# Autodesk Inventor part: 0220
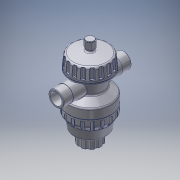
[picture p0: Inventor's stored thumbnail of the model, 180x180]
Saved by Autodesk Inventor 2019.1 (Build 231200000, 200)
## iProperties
Created: 2017-02
Part Number: 0220
Material: PVC-Piping
Document SubType Name: Modeling
Designer: KIM
Density: 1.4 g/cm^3
Appearance: PTFE
Mass: 92.6774 g
Surface Area: 199.44 cm^2
Volume: 66.1981 cm^3
Description: Universal Pressure Regulator UPR 550
Author: KIM
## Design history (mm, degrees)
sketch "Sketch4"
  geometry: L1 (0, 0)-(192, 0); L2 (192, 0)-(192, -8.05); L3 (190.3, -9.75)-(176.5, -9.75); L4 (176.5, -9.75)-(176.5, -6.75); L5 (176.5, -6.75)-(170.8, -6.75); L6 (170.8, -6.75)-(165.8, -40); L7 (165.8, -40)-(141.8, -42.5); L8 (105.5, -27.8)-(92.5, -45.5); L9 (57.7, -45.25)-(46.9, -38); L10 (46.9, -38)-(24.2, -34); L11 (24.2, -34)-(24.2, -22.8); L12 (24.2, -22.8)-(0, -22.8); L13 (0, -22.8)-(0, 0); L14 (192, -8.05)-(190.3, -8.05); L15 (190.3, -8.05)-(190.3, -9.75); L16 (141.8, -42.5)-(138.8, -42.5); L17 (138.8, -42.5)-(138.8, -41.8); L18 (138.8, -41.8)-(137.8, -41.8); L19 (137.8, -41.8)-(137.8, -42.5); L20 (137.8, -42.5)-(136, -42.5); L21 (136, -42.5)-(130, -30.5); L22 (72.7, -45.5)-(72.7, -44.55); L23 (72.7, -44.55)-(71.7, -44.55); L24 (71.7, -44.55)-(71.7, -45.25); L25 (92.5, -45.5)-(72.7, -45.5); L26 (71.7, -45.25)-(57.7, -45.25); L27 (116, 73)-(116, -73); L28 (132.625, -73)-(132.625, -53); L29 (132.625, -53)-(133.25, -53); L30 (133.25, -53)-(133.25, -52); L31 (133.25, -52)-(128.625, -52); L32 (128.625, -52)-(128.625, -73); L33 (128.625, -73)-(132.625, -73); L34 (105.5, -27.8)-(130, -30.5); 1 further point
  constraints: 68 end point, 19 perpendicular, 5 horizontal, 4 point on line, 4 vertical, 1 midpoint
  dimensions: "d51" = 192 distance of L1.start L1.end; "d53" = 19.5 diameter of L3 L1; "d54" = 1.7 distance of L14.end L3.start; "d55" = 1.7 distance of L2.end L14.end; "d56" = 15.5 distance between parallel lines of L2 L4; "d57" = 5.7 distance of L4.end L5.end; "d58" = 13.5 diameter of L5 L1; "d59" = 80 diameter of L6.end L1; "d60" = 5 horizontal distance of L5.end L6.end; "d61" = 2.5 vertical distance of L6.end L7.end; "d62" = 1.8 distance of L19.end L20.end; "d63" = 1 distance of L17.end L18.end; "d64" = 0.7 distance of L18.end L19.end; "d65" = 3 distance of L7.end L16.end; "d66" = 24 horizontal distance of L6.end L7.end; "d67" = 12 vertical distance of L20.end L21.end; "d68" = 6 horizontal distance of L20.end L21.end; "d70" = 24.5 horizontal distance of L8.start L21.end; "d71" = 2.7 vertical distance of L21.end L8.start; "d72" = 13 horizontal distance of L8.start L8.end; "d73" = 1 distance of L22.end L23.end; "d74" = 0.7 distance of L23.end L24.end; "d75" = 19.8 distance of L8.end L22.start; "d76" = 14 distance of L24.end L9.start; "d77" = 91 diameter of L25 L1; "d78" = 7.25 vertical distance of L9.start L9.end; "d79" = 10.8 horizontal distance of L9.start L9.end; "d80" = 22.7 horizontal distance of L9.end L10.end; "d81" = 68 diameter of L10.end L1; "d82" = 76 diameter of L9.end L1; "d83" = 45.6 diameter of L12 L1; "d84" = 146 distance of L27.start L27.end; "d85" = 116 distance of L1.start point (116, 0); "d86" = 20 distance of L28.start L28.end; "d87" = 33.249 diameter of L28 L27; "d88" = 4 distance of L32.end L28.start; "d90" = 34.5 diameter of L30 L27; "d91" = 1 distance of L29.end L30.end
revolve "Revolution2" stored, may be unused: angle "d92" = 90 deg
revolve "Revolution3" stored, may be unused: angle "d93" = 90 deg
sketch "Sketch5"
  geometry: L1 (0, 9.75)-(8.444, 4.875); L2 (8.444, 4.875)-(8.444, -4.875); L3 (8.444, -4.875)-(0, -9.75); L4 (0, -9.75)-(-8.444, -4.875); L5 (-8.444, -4.875)-(-8.444, 4.875); L6 (-8.444, 4.875)-(0, 9.75); L7 (0, 0)-(0, 9.75); 2 further points
  constraints: 14 end point, 1 coincident, 1 vertical, 1 vertical alignment, 14 other
extrude "Extrusion3" cut sketch "Sketch5" stored distance "d94" = 10; taper "d95" = 0 deg
fillet "Fillet5" dims "d96" = 5
fillet "Fillet6" dims "d97" = 4
sketch "Sketch6"
  geometry: L1 (0, 0)-(-66.727, 0); L2 (-42.5, -4)-(-42.5, 4); L3 (-42.5, 4)-(-41, 4); L4 (-39, 2)-(-39, -2); L5 (-41, -4)-(-42.5, -4); A1 r 2 centre (-41, 2) between (-39, 2) and (-41, 4); A2 r 2 centre (-41, -2) between (-41, -4) and (-39, -2); 2 further points
  constraints: 10 end point, 4 point on circle, 4 tangent, 3 perpendicular, 2 centre point, 1 equal radius, 1 horizontal, 1 horizontal alignment, 1 midpoint, 1 parallel, 1 point on line, 1 other
  dimensions: "d99" = 8 distance between parallel lines of L3 L5; "d100" = 3.5 distance from line of point (-42.5, 0) L4; "d101" = 2 radius of A1 (derived)
extrude "Extrusion4" cut sketch "Sketch6" distance "d102" = 48; taper "d103" = 0 deg
fillet "Fillet8" dims "d104" = 0.5
sketch "Sketch7"
  geometry: L1 (0, 0)-(-53.321, 0); L2 (-45.25, -2.75)-(-37.753, -2.75); L3 (-37.753, -2.75)-(-37.753, 2.75); L4 (-37.753, 2.75)-(-45.25, 2.75); L5 (-45.25, 2.75)-(-45.25, -2.75); C1 r 45.25 at (0, 0) reference; A1 r 37.853 centre (0, 0) between (-37.753, 2.75) and (-37.753, -2.75); 2 further points
  constraints: 10 end point, 2 horizontal, 2 parallel, 2 point on circle, 1 centre point, 1 horizontal alignment, 1 midpoint, 1 perpendicular, 1 tangent, 3 other
  dimensions: "d108" = 5.5 distance of L4.end L2.start
extrude "Extrusion5" cut sketch "Sketch7" distance "d109" = 44; taper "d110" = 0 deg
fillet "Fillet9" dims "d111" = 0.5
sketch "Sketch8"
  geometry: A1 r 22.8 centre (0, 0) between (-3.586, 22.516) and (3.586, 22.516) reference; A2 r 5 centre (0, 26) between (-3.586, 22.516) and (3.586, 22.516); 1 further point
  constraints: 4 point on circle, 1 centre point, 1 vertical alignment
  dimensions: "d115" = 5 radius of A2; "d116" = 26 distance of point (0, 0) A2.centre
extrude "Extrusion6" cut sketch "Sketch8" stored distance "d117" = 44; taper "d118" = 0 deg
pattern_circular "Circular Pattern5" dims angle "d120" = 360 deg
sketch "Sketch9"
  geometry: C1 r 12.624 at (0, 0) reference; C2 r 17.25 at (0, 0) reference; 1 further point
extrude "Extrusion7" join sketch "Sketch9" stored distance "d122" = 44; taper "d123" = 0 deg
chamfer "Chamfer5" distance "d124" = 1; stored, may be unused: second distance "d125" = 2, angle "d126" = 45 deg
fillet "Fillet10" dims "d127" = 1
fillet "Fillet11" dims "d128" = 1
pattern_circular "Circular Pattern6" dims "d130" = 360 deg
fillet "Fillet12" dims "d132" = 3
body "Solid2"
pattern_circular "Circular Pattern3" dims angle "d106" = 360 deg
pattern_circular "Circular Pattern4" dims angle "d113" = 360 deg
node "Projected Loop1"
other parameters: "d52" = 92
